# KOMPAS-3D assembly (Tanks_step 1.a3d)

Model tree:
1. Plane XY
2. Plane ZX
3. Plane ZY
4. X Axis
5. Y Axis
6. Z Axis
7. Origin
8. Point:1
     X = -6791.83; Y = -1500; Z = 1.7112e-08; Coordinate.X = -6791.83; Coordinate.Y = -1500; Coordinate.Z = 1.7112e-08
9. Point:2
     X = -1606; Y = -500; Move.X = -500; Distance = 500
10. Point:3
     X = -1606; Y = -2500; Z = 700; Move.X = -500; Move.Z = 4.09273e-09; Distance = 500
11. Point:9  (labels: C:\Program Files\ASCON\KOMPAS-3D V10\Sys\graphic.lyt)
     X = -3769.83; Y = 762.724; Z = 3112; Move.Z = 500; Distance = 500; Orientation = 2

Referenced files in C:\Documents and Settings\kashirsky\Мои документы\Camtasia Studio\Pipelines3D\Tanks\: Tank 2.a3d, Tank 1.a3d, Piping_Joint_150_1000.m3d, Piping_Flange_150_1000.m3d, Piping_Joint_50_1000.m3d, Piping_Flange_50_1000.m3d, Tanks_step 1.a3d
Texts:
  Three Point Plane
  Plane at Angle
  Line and Point Plane
  Axis through Two Vertices
  Axis of Feature
  Axis of Conical Surface
  Axis through Edge
  Trim by Surface
  Trim by Sketch
  Intersection Axis of Two Planes
  Two Line Plane
  Line and Face Plane
  Pattern by Sample
  Point in CM
  Feature with No History
  Linear Dimension from Line to Point
  Surface Finish Symbol
  Geometric Tolerance Symbol
  Текст на чертеже
  Линия-выноска #1
  Линия-выноска #2
  Линия-выноска #3
  Отклонения формы и база
  Марка координационной оси
  Марка/позиционное обозначение с линией-выноской
  Марка/позиционное обозначение на линии
  Марка/позиционное обозначение без линии-выноски
  Tank 2
  Tank 1
  Joint Dn 150
  Steel ASTM A295
  Flange Dn 150
  Прокладка Dy 50
  Flange Dn 50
